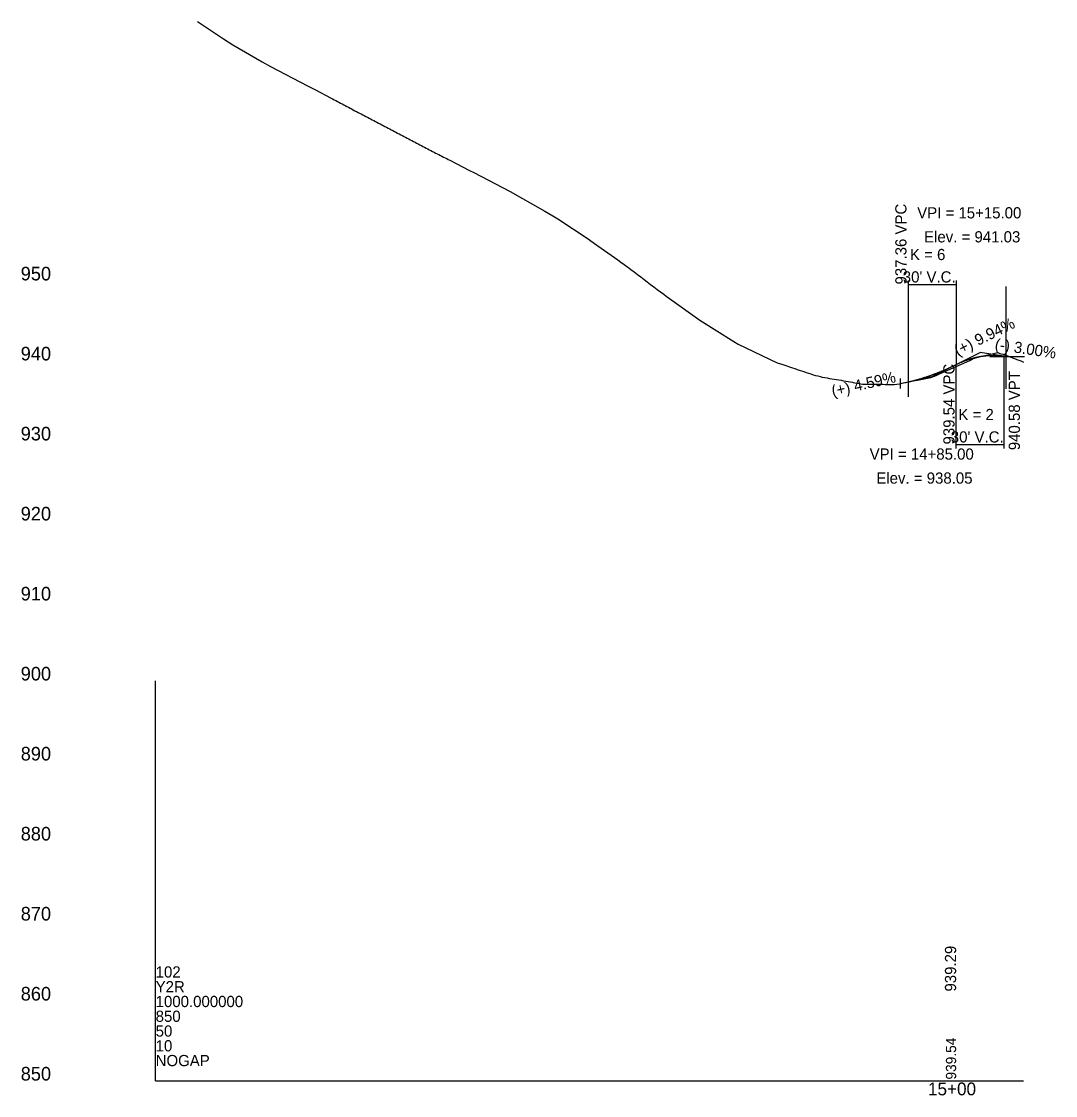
# Model space of a CAD drawing. Extents: x 1558113 to 1562835, y 1129435 to 1135883.
# Drawn here: x 1558113 to 1558758, y 1129435 to 1130106 of the extents above; entities that cross this region are included whole.
import ezdxf

# ---------------------------------------------------------------- set-up
doc = ezdxf.new("R2010")
doc.units = 0
for name, color, linetype in [('BR_USER NOTES', 7, 'Continuous'), ('RD_DDB_ElevTX', 7, 'Continuous'), ('RD_DDB_GradeTX', 7, 'Continuous'), ('RD_DDB_Profile_EX', 7, 'Continuous'), ('RD_DDB_Profile_Lbl', 7, 'Continuous'), ('RD_DDB_Profile_PR', 7, 'Continuous'), ('RD_DDB_StaTX', 7, 'Continuous'), ('RD_DDB_StripGrade', 7, 'Continuous'), ('RD_DDB_VCLbl', 7, 'Continuous'), ('RD_GPK_Profile_Cell', 7, 'Continuous')]:
    doc.layers.add(name, color=color, linetype=linetype)

msp = doc.modelspace()

# ---------------------------------------------------------------- linework, layer by layer
at = {"layer": 'BR_USER NOTES'}
for p, q in [((1558727.36, 1129940.37), (1558727.36, 1129876.44)), ((1558717.47, 1129896.59), (1558739.17, 1129896.59)), ((1558666.37, 1129893.73), (1558666.37, 1129871.24)), ((1558661.37, 1129882.89), (1558661.37, 1129876.52)), ((1558661.37, 1129879.61), (1558666.37, 1129880.63))]:
    msp.add_line(p, q, dxfattribs=at)
at = {"layer": 'RD_DDB_GradeTX'}
for p, q in [((1558681.37, 1129884.08), (1558711.37, 1129898.98)), ((1558727.36, 1129896.59), (1558711.37, 1129898.98)), ((1558666.37, 1129880.63), (1558681.37, 1129884.08))]:
    msp.add_line(p, q, dxfattribs=at)
at = {"layer": 'RD_DDB_Profile_EX'}
msp.add_lwpolyline([(1558222.59, 1130105.9), (1558238.77, 1130095.04), (1558244.56, 1130091.32), (1558262.99, 1130080.62), (1558268.11, 1130077.82), (1558291.22, 1130065.7), (1558294.88, 1130063.82), (1558295.77, 1130063.42), (1558305.93, 1130058.04), (1558306.92, 1130057.52), (1558307.91, 1130057), (1558308.9, 1130056.47), (1558309.89, 1130055.95), (1558310.88, 1130055.42), (1558311.87, 1130054.9), (1558312.86, 1130054.37), (1558313.85, 1130053.84), (1558314.84, 1130053.32), (1558315.83, 1130052.79), (1558316.82, 1130052.26), (1558317.81, 1130051.74), (1558318.8, 1130051.21), (1558319.79, 1130050.68), (1558320.78, 1130050.15), (1558321.29, 1130049.87), (1558321.77, 1130049.66), (1558322.93, 1130049.11), (1558323.74, 1130048.66), (1558324.73, 1130048.15), (1558325.72, 1130047.63), (1558326.71, 1130047.11), (1558327.7, 1130046.59), (1558328.69, 1130046.07), (1558329.68, 1130045.55), (1558330.67, 1130045.02), (1558331.66, 1130044.5), (1558332.65, 1130043.98), (1558333.64, 1130043.45), (1558334.63, 1130042.93), (1558335.62, 1130042.41), (1558336.61, 1130041.88), (1558337.6, 1130041.36), (1558338.59, 1130040.83), (1558339.58, 1130040.31), (1558340.57, 1130039.78), (1558341.56, 1130039.25), (1558342.55, 1130038.73), (1558343.54, 1130038.2), (1558344.09, 1130037.91), (1558344.52, 1130037.7), (1558345.55, 1130037.19), (1558346.5, 1130036.7), (1558347.49, 1130036.18), (1558348.48, 1130035.67), (1558349.47, 1130035.15), (1558350.46, 1130034.63), (1558351.45, 1130034.12), (1558352.44, 1130033.6), (1558353.43, 1130033.08), (1558354.42, 1130032.56), (1558355.41, 1130032.04), (1558356.4, 1130031.52), (1558357.39, 1130030.99), (1558358.38, 1130030.47), (1558359.37, 1130029.95), (1558360.36, 1130029.42), (1558361.35, 1130028.9), (1558362.34, 1130028.37), (1558363.33, 1130027.85), (1558364.31, 1130027.32), (1558365.3, 1130026.8), (1558366.29, 1130026.27), (1558367.28, 1130025.74), (1558368.27, 1130025.22), (1558369.26, 1130024.72), (1558370.25, 1130024.21), (1558371.24, 1130023.71), (1558372.23, 1130023.21), (1558373.22, 1130022.71), (1558374.21, 1130022.2), (1558375.2, 1130021.7), (1558376.19, 1130021.2), (1558377.18, 1130020.69), (1558378.17, 1130020.19), (1558379.16, 1130019.69), (1558380.15, 1130019.19), (1558384.13, 1130017.16), (1558392.47, 1130012.87), (1558395.17, 1130011.51), (1558417.79, 1129999.74), (1558439.37, 1129987.46), (1558444.43, 1129984.55), (1558447.64, 1129982.5), (1558466.44, 1129970.06), (1558468.5, 1129968.7), (1558468.81, 1129968.49), (1558470.55, 1129967.24), (1558472.05, 1129966.18), (1558472.61, 1129965.77), (1558474.67, 1129964.29), (1558476.73, 1129962.81), (1558478.79, 1129961.33), (1558480.84, 1129959.85), (1558482.9, 1129958.38), (1558484.96, 1129956.9), (1558487.02, 1129955.42), (1558489.07, 1129953.94), (1558491.31, 1129952.34), (1558491.91, 1129951.9), (1558493.19, 1129950.93), (1558495.25, 1129949.38), (1558497.31, 1129947.82), (1558499.36, 1129946.27), (1558501.42, 1129944.72), (1558503.48, 1129943.17), (1558505.54, 1129941.61), (1558507.59, 1129940.06), (1558509.65, 1129938.51), (1558511.71, 1129936.96), (1558513.77, 1129935.41), (1558515.24, 1129934.34), (1558515.82, 1129933.92), (1558534.82, 1129920.25), (1558536.28, 1129919.25), (1558557.47, 1129905.96), (1558560.25, 1129904.23), (1558579.86, 1129894.95), (1558584.52, 1129892.66), (1558588.17, 1129891.44), (1558594.09, 1129889.48), (1558595.54, 1129889), (1558596.98, 1129888.52), (1558598.43, 1129888.04), (1558599.88, 1129887.55), (1558601.33, 1129887.07), (1558602.77, 1129886.59), (1558604.22, 1129886.11), (1558605.67, 1129885.62), (1558607.12, 1129885.14), (1558608.57, 1129884.75), (1558610.01, 1129884.36), (1558611.46, 1129883.97), (1558612.59, 1129883.66), (1558612.91, 1129883.61), (1558614.36, 1129883.37), (1558615.81, 1129883.13), (1558617.25, 1129882.88), (1558618.7, 1129882.64), (1558620.15, 1129882.4), (1558621.6, 1129882.16), (1558623.04, 1129881.91), (1558624.49, 1129881.67), (1558625.94, 1129881.42), (1558627.39, 1129881.18), (1558628.84, 1129880.94), (1558630.28, 1129880.69), (1558631.73, 1129880.45), (1558632.12, 1129880.38), (1558633.18, 1129880.18), (1558634.63, 1129879.9), (1558636.08, 1129879.63), (1558637.81, 1129879.29), (1558638.97, 1129879.29), (1558640.42, 1129879.29), (1558641.87, 1129879.29), (1558642.54, 1129879.28), (1558643.31, 1129879.27), (1558644.76, 1129879.25), (1558646.21, 1129879.23), (1558647.66, 1129879.21), (1558649.11, 1129879.19), (1558650.55, 1129879.17), (1558652, 1129879.14), (1558653.45, 1129879.12), (1558654.9, 1129879.1), (1558656.35, 1129879.07), (1558657.79, 1129879.05), (1558659.24, 1129879.27), (1558660.98, 1129879.53), (1558662.14, 1129879.77), (1558663.59, 1129880.06), (1558665.03, 1129880.36), (1558666.48, 1129880.65), (1558667.93, 1129880.95), (1558669.38, 1129881.24), (1558670.82, 1129881.53), (1558672.27, 1129881.83), (1558680.51, 1129883.48), (1558683.83, 1129884.71), (1558685.99, 1129885.75), (1558704.88, 1129894.05), (1558707.05, 1129895.32), (1558711.5, 1129896.52), (1558722.4, 1129899.03), (1558723.6, 1129898.48), (1558724.38, 1129898.24), (1558725.68, 1129898.05), (1558734.91, 1129894.49), (1558736.74, 1129893.78), (1558738.36, 1129893.04)], dxfattribs=at)
at = {"layer": 'RD_DDB_Profile_PR'}
msp.add_line((1558726.37, 1129896.73), (1558727.36, 1129896.59), dxfattribs=at)
for points in [[(1558696.37, 1129891.53), (1558696.97, 1129891.82), (1558697.57, 1129892.11), (1558698.17, 1129892.39), (1558698.77, 1129892.66), (1558699.37, 1129892.92), (1558699.97, 1129893.18), (1558700.57, 1129893.43), (1558701.17, 1129893.67), (1558701.77, 1129893.9), (1558702.37, 1129894.12), (1558702.97, 1129894.34), (1558703.57, 1129894.55), (1558704.17, 1129894.75), (1558704.77, 1129894.94), (1558705.37, 1129895.13), (1558705.97, 1129895.31), (1558706.57, 1129895.48), (1558707.17, 1129895.64), (1558707.77, 1129895.79), (1558708.37, 1129895.94), (1558708.97, 1129896.08), (1558709.57, 1129896.21), (1558710.17, 1129896.33), (1558710.77, 1129896.45), (1558711.37, 1129896.56), (1558711.97, 1129896.66), (1558712.57, 1129896.75), (1558713.17, 1129896.84), (1558713.77, 1129896.91), (1558714.37, 1129896.98), (1558714.97, 1129897.04), (1558715.57, 1129897.1), (1558716.17, 1129897.14), (1558716.77, 1129897.18), (1558717.37, 1129897.21), (1558717.97, 1129897.23), (1558718.57, 1129897.25), (1558719.17, 1129897.25), (1558719.77, 1129897.25), (1558720.37, 1129897.25), (1558720.97, 1129897.23), (1558721.57, 1129897.21), (1558722.17, 1129897.17), (1558722.77, 1129897.13), (1558723.37, 1129897.09), (1558723.97, 1129897.03), (1558724.57, 1129896.97), (1558725.17, 1129896.9), (1558725.77, 1129896.82), (1558726.37, 1129896.73)], [(1558666.37, 1129880.63), (1558666.97, 1129880.77), (1558667.57, 1129880.91), (1558668.17, 1129881.06), (1558668.77, 1129881.21), (1558669.37, 1129881.36), (1558669.97, 1129881.52), (1558670.57, 1129881.67), (1558671.17, 1129881.84), (1558671.77, 1129882), (1558672.37, 1129882.17), (1558672.97, 1129882.34), (1558673.57, 1129882.52), (1558674.17, 1129882.69), (1558674.77, 1129882.87), (1558675.37, 1129883.06), (1558675.97, 1129883.25), (1558676.57, 1129883.44), (1558677.17, 1129883.63), (1558677.77, 1129883.83), (1558678.37, 1129884.03), (1558678.97, 1129884.23), (1558679.57, 1129884.44), (1558680.17, 1129884.65), (1558680.77, 1129884.86), (1558681.37, 1129885.08), (1558681.97, 1129885.3), (1558682.57, 1129885.52), (1558683.17, 1129885.75), (1558683.77, 1129885.98), (1558684.37, 1129886.21), (1558684.97, 1129886.44), (1558685.57, 1129886.68), (1558686.17, 1129886.92), (1558686.77, 1129887.17), (1558687.37, 1129887.42), (1558687.97, 1129887.67), (1558688.57, 1129887.92), (1558689.17, 1129888.18), (1558689.77, 1129888.44), (1558690.37, 1129888.71), (1558690.97, 1129888.98), (1558691.57, 1129889.25), (1558692.17, 1129889.52), (1558692.77, 1129889.8), (1558693.37, 1129890.08), (1558693.97, 1129890.36), (1558694.57, 1129890.65), (1558695.17, 1129890.94), (1558695.77, 1129891.23), (1558696.37, 1129891.53)]]:
    msp.add_spline(points, degree=3, dxfattribs=at)
at = {"layer": 'RD_DDB_VCLbl'}
for p, q in [((1558666.37, 1129944.03), (1558666.37, 1129880.63)), ((1558696.37, 1129944.03), (1558696.37, 1129891.53)), ((1558666.37, 1129941.53), (1558696.37, 1129941.53)), ((1558726.37, 1129839.03), (1558726.37, 1129896.73)), ((1558696.37, 1129839.03), (1558696.37, 1129891.53)), ((1558696.37, 1129841.53), (1558726.37, 1129841.53))]:
    msp.add_line(p, q, dxfattribs=at)
at = {"layer": 'RD_GPK_Profile_Cell'}
for q in [(1558196.37, 1129693.84), (1558738.36, 1129443.84), (1558196.37, 1129443.84)]:
    msp.add_line((1558196.37, 1129443.84), q, dxfattribs=at)

# ---------------------------------------------------------------- texts
at = {"layer": 'RD_DDB_ElevTX'}
for s, p in [('950', (1558112.09, 1129944.09)), ('940', (1558112.09, 1129894.09)), ('930', (1558112.09, 1129844.09)), ('920', (1558112.09, 1129794.09)), ('910', (1558112.09, 1129744.09)), ('900', (1558112.09, 1129694.09)), ('890', (1558112.09, 1129644.09)), ('880', (1558112.09, 1129594.09)), ('870', (1558112.09, 1129544.09)), ('860', (1558112.09, 1129494.09)), ('850', (1558112.09, 1129444.09))]:
    msp.add_text(s, height=8.5, dxfattribs=at).set_placement(p)
at = {"layer": 'RD_DDB_GradeTX'}
for s, rotation, p in [('(+) 9.94%', 26.4241, (1558697.27, 1129896.73)), ('(-) 3.00%', 351.46923, (1558720.22, 1129900.91)), ('(+) 4.59%', 12.93644, (1558619.41, 1129871.41))]:
    msp.add_text(s, height=7, rotation=rotation, dxfattribs=at).set_placement(p)
at = {"layer": 'RD_DDB_Profile_Lbl'}
for s, p in [('VPI = 15+15.00', (1558672.05, 1129982.84)), ('Elev. = 941.03', (1558676.34, 1129967.84)), ('VPI = 14+85.00', (1558642.34, 1129832.08)), ('Elev. = 938.05', (1558646.51, 1129817.08))]:
    msp.add_text(s, height=7, dxfattribs=at).set_placement(p)
at = {"layer": 'RD_DDB_StaTX'}
msp.add_text('15+00', height=8, dxfattribs=at).set_placement((1558678.77, 1129434.84))
at = {"layer": 'RD_DDB_StripGrade'}
for s, height, p in [('937.36 VPC', 7, (1558665.37, 1129941.53)), ('939.54 VPC', 7, (1558695.37, 1129841.53)), ('940.58 VPT', 7, (1558736.21, 1129837.98)), ('939.29', 7, (1558696.37, 1129499.68)), ('939.54', 6.4, (1558696.37, 1129444.71))]:
    msp.add_text(s, height=height, rotation=90, dxfattribs=at).set_placement(p)
at = {"layer": 'RD_DDB_VCLbl'}
for s, p in [('K = 6', (1558667.52, 1129956.78)), ("30' V.C.", (1558663.05, 1129942.78)), ('K = 2', (1558697.77, 1129856.78)), ("30' V.C.", (1558693.05, 1129842.78))]:
    msp.add_text(s, height=7, dxfattribs=at).set_placement(p)
at = {"layer": 'RD_GPK_Profile_Cell'}
for s, p in [('102', (1558196.37, 1129508.45)), ('Y2R', (1558196.37, 1129499.22)), ('1000.000000', (1558196.37, 1129489.99)), ('850', (1558196.37, 1129480.76)), ('50', (1558196.37, 1129471.53)), ('10', (1558196.37, 1129462.3)), ('NOGAP', (1558196.37, 1129453.07))]:
    msp.add_text(s, height=7, dxfattribs=at).set_placement(p)

doc.saveas('drawing.dxf')
